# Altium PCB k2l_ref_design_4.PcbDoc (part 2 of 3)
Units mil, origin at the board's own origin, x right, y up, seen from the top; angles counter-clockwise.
Board outline 8000 x 6000 mil, 2 copper layers (Top Layer, Bottom Layer), stack 62 mil thick; 620 components, 466 nets, 2754 pads, 0 vias.
Unrouted connection lines stored in the file: 183.
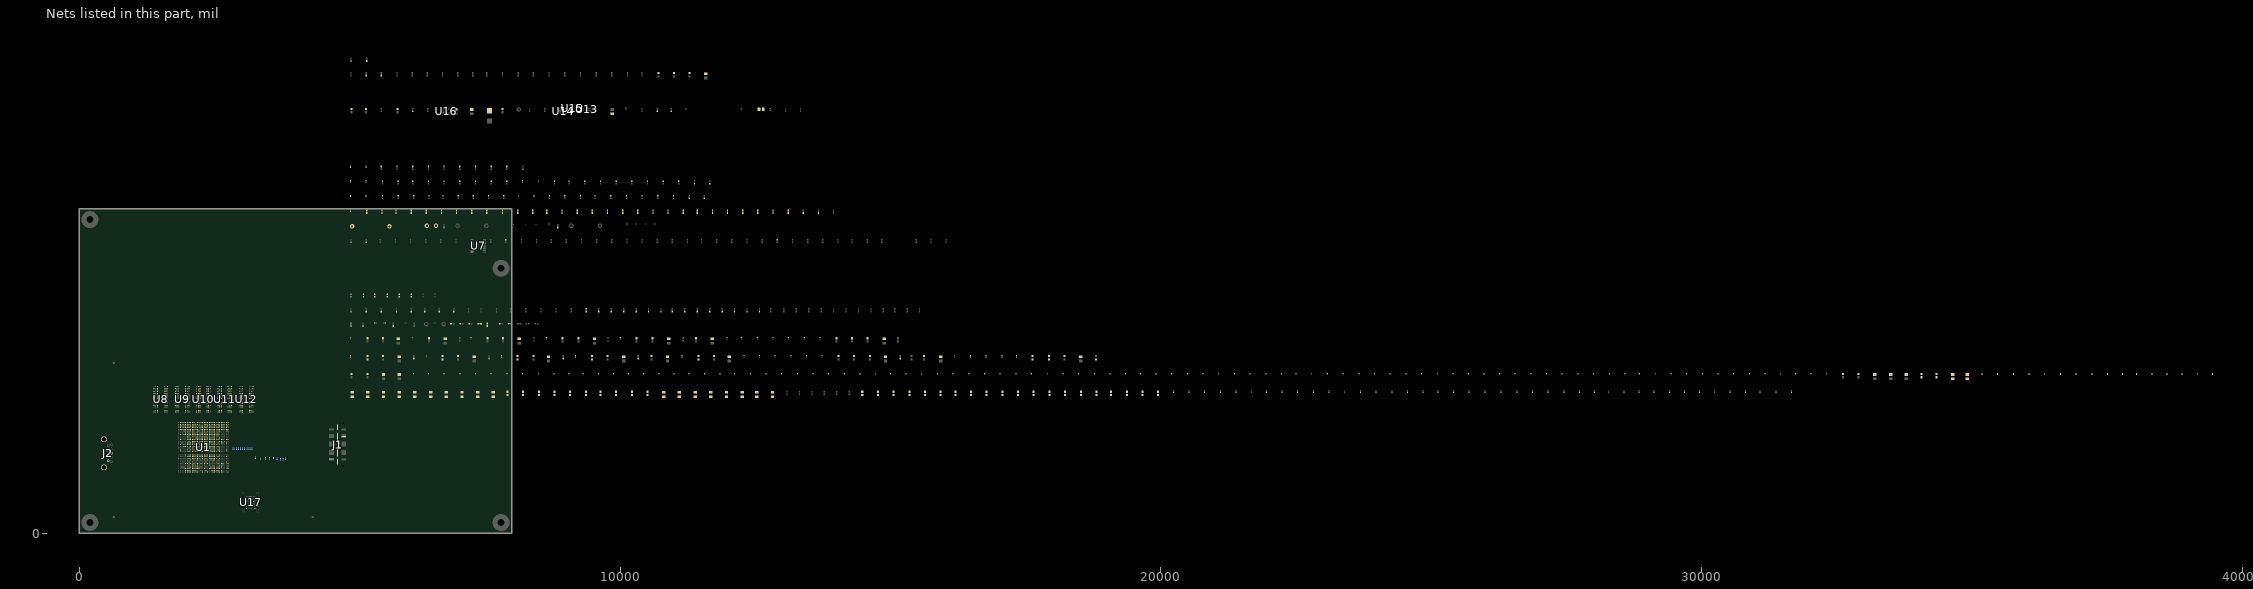
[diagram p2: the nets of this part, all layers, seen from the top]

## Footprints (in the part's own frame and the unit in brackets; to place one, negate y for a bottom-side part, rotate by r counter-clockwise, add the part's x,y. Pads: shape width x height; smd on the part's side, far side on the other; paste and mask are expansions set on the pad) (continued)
BGA900C80P30X30_2500X2500X355 [mm] "BGA, 900-Leads, Body 25.0x25.0mm,  Pitch 0.80mm"
  round 0.45 smd: A1(-11.6,11.6) A2(-10.8,11.6) A3(-10,11.6) A4(-9.2,11.6) A5(-8.4,11.6) A6(-7.6,11.6) A7(-6.8,11.6) A8(-6,11.6) A9(-5.2,11.6) A10(-4.4,11.6) A11(-3.6,11.6) A12(-2.8,11.6) A13(-2,11.6) A14(-1.2,11.6) A15(-0.4,11.6) A16(0.4,11.6) A17(1.2,11.6) A18(2,11.6) A19(2.8,11.6) A20(3.6,11.6) A21(4.4,11.6) A22(5.2,11.6) A23(6,11.6) A24(6.8,11.6) A25(7.6,11.6) A26(8.4,11.6) A27(9.2,11.6) A28(10,11.6) A29(10.8,11.6) A30(11.6,11.6) AA1(-11.6,-4.4) AA2(-10.8,-4.4) AA3(-10,-4.4) AA4(-9.2,-4.4) AA5(-8.4,-4.4) AA6(-7.6,-4.4) AA7(-6.8,-4.4) AA8(-6,-4.4) AA9(-5.2,-4.4) AA10(-4.4,-4.4) AA11(-3.6,-4.4) AA12(-2.8,-4.4) AA13(-2,-4.4) AA14(-1.2,-4.4) AA15(-0.4,-4.4) AA16(0.4,-4.4) AA17(1.2,-4.4) AA18(2,-4.4) AA19(2.8,-4.4) AA20(3.6,-4.4) AA21(4.4,-4.4) AA22(5.2,-4.4) AA23(6,-4.4) AA24(6.8,-4.4) AA25(7.6,-4.4) AA26(8.4,-4.4) AA27(9.2,-4.4) AA28(10,-4.4) AA29(10.8,-4.4) AA30(11.6,-4.4) AB1(-11.6,-5.2) AB2(-10.8,-5.2) AB3(-10,-5.2) AB4(-9.2,-5.2) AB5(-8.4,-5.2) AB6(-7.6,-5.2) AB7(-6.8,-5.2) AB8(-6,-5.2) AB9(-5.2,-5.2) AB10(-4.4,-5.2) AB11(-3.6,-5.2) AB12(-2.8,-5.2) AB13(-2,-5.2) AB14(-1.2,-5.2) AB15(-0.4,-5.2) AB16(0.4,-5.2) AB17(1.2,-5.2) AB18(2,-5.2) AB19(2.8,-5.2) AB20(3.6,-5.2) AB21(4.4,-5.2) AB22(5.2,-5.2) AB23(6,-5.2) AB24(6.8,-5.2) AB25(7.6,-5.2) AB26(8.4,-5.2) AB27(9.2,-5.2) AB28(10,-5.2) AB29(10.8,-5.2) AB30(11.6,-5.2) AC1(-11.6,-6) AC2(-10.8,-6) AC3(-10,-6) AC4(-9.2,-6) AC5(-8.4,-6) AC6(-7.6,-6) AC7(-6.8,-6) AC8(-6,-6) AC9(-5.2,-6) AC10(-4.4,-6) AC11(-3.6,-6) AC12(-2.8,-6) AC13(-2,-6) AC14(-1.2,-6) AC15(-0.4,-6) AC16(0.4,-6) AC17(1.2,-6) AC18(2,-6) AC19(2.8,-6) AC20(3.6,-6) AC21(4.4,-6) AC22(5.2,-6) AC23(6,-6) AC24(6.8,-6) AC25(7.6,-6) AC26(8.4,-6) AC27(9.2,-6) AC28(10,-6) AC29(10.8,-6) AC30(11.6,-6) AD1(-11.6,-6.8) AD2(-10.8,-6.8) AD3(-10,-6.8) AD4(-9.2,-6.8) AD5(-8.4,-6.8) AD6(-7.6,-6.8) AD7(-6.8,-6.8) AD8(-6,-6.8) AD9(-5.2,-6.8) AD10(-4.4,-6.8) AD11(-3.6,-6.8) AD12(-2.8,-6.8) AD13(-2,-6.8) AD14(-1.2,-6.8) AD15(-0.4,-6.8) AD16(0.4,-6.8) AD17(1.2,-6.8) AD18(2,-6.8) AD19(2.8,-6.8) AD20(3.6,-6.8) AD21(4.4,-6.8) AD22(5.2,-6.8) AD23(6,-6.8) AD24(6.8,-6.8) AD25(7.6,-6.8) AD26(8.4,-6.8) AD27(9.2,-6.8) AD28(10,-6.8) AD29(10.8,-6.8) AD30(11.6,-6.8) AE1(-11.6,-7.6) AE2(-10.8,-7.6) AE3(-10,-7.6) AE4(-9.2,-7.6) AE5(-8.4,-7.6) AE6(-7.6,-7.6) AE7(-6.8,-7.6) AE8(-6,-7.6) AE9(-5.2,-7.6) AE10(-4.4,-7.6) AE11(-3.6,-7.6) AE12(-2.8,-7.6) AE13(-2,-7.6) AE14(-1.2,-7.6) AE15(-0.4,-7.6) AE16(0.4,-7.6) AE17(1.2,-7.6) AE18(2,-7.6) AE19(2.8,-7.6) AE20(3.6,-7.6) AE21(4.4,-7.6) AE22(5.2,-7.6) AE23(6,-7.6) AE24(6.8,-7.6) AE25(7.6,-7.6) AE26(8.4,-7.6) AE27(9.2,-7.6) AE28(10,-7.6) AE29(10.8,-7.6) AE30(11.6,-7.6) AF1(-11.6,-8.4) AF2(-10.8,-8.4) AF3(-10,-8.4) AF4(-9.2,-8.4) AF5(-8.4,-8.4) AF6(-7.6,-8.4) AF7(-6.8,-8.4) AF8(-6,-8.4) AF9(-5.2,-8.4) AF10(-4.4,-8.4) AF11(-3.6,-8.4) AF12(-2.8,-8.4) AF13(-2,-8.4) AF14(-1.2,-8.4) AF15(-0.4,-8.4) AF16(0.4,-8.4) AF17(1.2,-8.4) AF18(2,-8.4) AF19(2.8,-8.4) AF20(3.6,-8.4) AF21(4.4,-8.4) AF22(5.2,-8.4) AF23(6,-8.4) AF24(6.8,-8.4) AF25(7.6,-8.4) AF26(8.4,-8.4) AF27(9.2,-8.4) AF28(10,-8.4) AF29(10.8,-8.4) AF30(11.6,-8.4) AG1(-11.6,-9.2) AG2(-10.8,-9.2) AG3(-10,-9.2) AG4(-9.2,-9.2) AG5(-8.4,-9.2) AG6(-7.6,-9.2) AG7(-6.8,-9.2) AG8(-6,-9.2) AG9(-5.2,-9.2) AG10(-4.4,-9.2) AG11(-3.6,-9.2) AG12(-2.8,-9.2) AG13(-2,-9.2) AG14(-1.2,-9.2) AG15(-0.4,-9.2) AG16(0.4,-9.2) AG17(1.2,-9.2) AG18(2,-9.2) AG19(2.8,-9.2) AG20(3.6,-9.2) AG21(4.4,-9.2) AG22(5.2,-9.2) AG23(6,-9.2) AG24(6.8,-9.2) AG25(7.6,-9.2) AG26(8.4,-9.2) AG27(9.2,-9.2) AG28(10,-9.2) AG29(10.8,-9.2) AG30(11.6,-9.2) AH1(-11.6,-10) AH2(-10.8,-10) AH3(-10,-10) AH4(-9.2,-10) AH5(-8.4,-10) AH6(-7.6,-10) AH7(-6.8,-10) AH8(-6,-10) AH9(-5.2,-10) AH10(-4.4,-10) AH11(-3.6,-10) AH12(-2.8,-10) AH13(-2,-10) AH14(-1.2,-10) AH15(-0.4,-10) AH16(0.4,-10) AH17(1.2,-10) AH18(2,-10) AH19(2.8,-10) AH20(3.6,-10) AH21(4.4,-10) AH22(5.2,-10) AH23(6,-10) AH24(6.8,-10) AH25(7.6,-10) AH26(8.4,-10) AH27(9.2,-10) AH28(10,-10) AH29(10.8,-10) AH30(11.6,-10) AJ1(-11.6,-10.8) AJ2(-10.8,-10.8) AJ3(-10,-10.8) AJ4(-9.2,-10.8) AJ5(-8.4,-10.8) AJ6(-7.6,-10.8) AJ7(-6.8,-10.8) AJ8(-6,-10.8) AJ9(-5.2,-10.8) AJ10(-4.4,-10.8) AJ11(-3.6,-10.8) AJ12(-2.8,-10.8) AJ13(-2,-10.8) AJ14(-1.2,-10.8) AJ15(-0.4,-10.8) AJ16(0.4,-10.8) AJ17(1.2,-10.8) AJ18(2,-10.8) AJ19(2.8,-10.8) AJ20(3.6,-10.8) AJ21(4.4,-10.8) AJ22(5.2,-10.8) AJ23(6,-10.8) AJ24(6.8,-10.8) AJ25(7.6,-10.8) AJ26(8.4,-10.8) AJ27(9.2,-10.8) AJ28(10,-10.8) AJ29(10.8,-10.8) AJ30(11.6,-10.8) AK1(-11.6,-11.6) AK2(-10.8,-11.6) AK3(-10,-11.6) AK4(-9.2,-11.6) AK5(-8.4,-11.6) AK6(-7.6,-11.6) AK7(-6.8,-11.6) AK8(-6,-11.6) AK9(-5.2,-11.6) AK10(-4.4,-11.6) AK11(-3.6,-11.6) AK12(-2.8,-11.6) AK13(-2,-11.6) AK14(-1.2,-11.6) AK15(-0.4,-11.6) AK16(0.4,-11.6) AK17(1.2,-11.6) AK18(2,-11.6) AK19(2.8,-11.6) AK20(3.6,-11.6) AK21(4.4,-11.6) AK22(5.2,-11.6) AK23(6,-11.6) AK24(6.8,-11.6) AK25(7.6,-11.6) AK26(8.4,-11.6) AK27(9.2,-11.6) AK28(10,-11.6) AK29(10.8,-11.6) AK30(11.6,-11.6) B1(-11.6,10.8) B2(-10.8,10.8) B3(-10,10.8) B4(-9.2,10.8) B5(-8.4,10.8) B6(-7.6,10.8) B7(-6.8,10.8) B8(-6,10.8) B9(-5.2,10.8) B10(-4.4,10.8) B11(-3.6,10.8) B12(-2.8,10.8) B13(-2,10.8) B14(-1.2,10.8) B15(-0.4,10.8) B16(0.4,10.8) B17(1.2,10.8) B18(2,10.8) B19(2.8,10.8) B20(3.6,10.8) B21(4.4,10.8) B22(5.2,10.8) B23(6,10.8) B24(6.8,10.8) B25(7.6,10.8) B26(8.4,10.8) B27(9.2,10.8) B28(10,10.8) B29(10.8,10.8) B30(11.6,10.8) C1(-11.6,10) C2(-10.8,10) C3(-10,10) C4(-9.2,10) C5(-8.4,10) C6(-7.6,10) C7(-6.8,10) C8(-6,10) C9(-5.2,10) C10(-4.4,10) C11(-3.6,10) C12(-2.8,10) C13(-2,10) C14(-1.2,10) C15(-0.4,10) C16(0.4,10) C17(1.2,10) C18(2,10) C19(2.8,10) C20(3.6,10) C21(4.4,10) C22(5.2,10) C23(6,10) C24(6.8,10) C25(7.6,10) C26(8.4,10) C27(9.2,10) C28(10,10) C29(10.8,10) C30(11.6,10) D1(-11.6,9.2) D2(-10.8,9.2) D3(-10,9.2) D4(-9.2,9.2) D5(-8.4,9.2) D6(-7.6,9.2) D7(-6.8,9.2) D8(-6,9.2) D9(-5.2,9.2) D10(-4.4,9.2) D11(-3.6,9.2) D12(-2.8,9.2) D13(-2,9.2) D14(-1.2,9.2) D15(-0.4,9.2) D16(0.4,9.2) D17(1.2,9.2) D18(2,9.2) D19(2.8,9.2) D20(3.6,9.2) D21(4.4,9.2) D22(5.2,9.2) D23(6,9.2) D24(6.8,9.2) D25(7.6,9.2) D26(8.4,9.2) D27(9.2,9.2) D28(10,9.2) D29(10.8,9.2) D30(11.6,9.2) E1(-11.6,8.4) E2(-10.8,8.4) E3(-10,8.4) E4(-9.2,8.4) E5(-8.4,8.4) E6(-7.6,8.4) E7(-6.8,8.4) E8(-6,8.4) E9(-5.2,8.4) E10(-4.4,8.4) E11(-3.6,8.4) E12(-2.8,8.4) E13(-2,8.4) E14(-1.2,8.4) E15(-0.4,8.4) E16(0.4,8.4) E17(1.2,8.4) E18(2,8.4) E19(2.8,8.4) E20(3.6,8.4) E21(4.4,8.4) E22(5.2,8.4) E23(6,8.4) E24(6.8,8.4) E25(7.6,8.4) E26(8.4,8.4) E27(9.2,8.4) E28(10,8.4) E29(10.8,8.4) E30(11.6,8.4) F1(-11.6,7.6) F2(-10.8,7.6) F3(-10,7.6) F4(-9.2,7.6) F5(-8.4,7.6) F6(-7.6,7.6) F7(-6.8,7.6) F8(-6,7.6) F9(-5.2,7.6) F10(-4.4,7.6) F11(-3.6,7.6) F12(-2.8,7.6) F13(-2,7.6) F14(-1.2,7.6) F15(-0.4,7.6) F16(0.4,7.6) F17(1.2,7.6) F18(2,7.6) F19(2.8,7.6) F20(3.6,7.6) F21(4.4,7.6) F22(5.2,7.6) F23(6,7.6) F24(6.8,7.6) F25(7.6,7.6) F26(8.4,7.6) F27(9.2,7.6) F28(10,7.6) F29(10.8,7.6) F30(11.6,7.6) G1(-11.6,6.8) G2(-10.8,6.8) G3(-10,6.8) G4(-9.2,6.8) G5(-8.4,6.8) G6(-7.6,6.8) G7(-6.8,6.8) G8(-6,6.8) G9(-5.2,6.8) G10(-4.4,6.8) G11(-3.6,6.8) G12(-2.8,6.8) G13(-2,6.8) G14(-1.2,6.8) G15(-0.4,6.8) G16(0.4,6.8) G17(1.2,6.8) G18(2,6.8) G19(2.8,6.8) G20(3.6,6.8) G21(4.4,6.8) G22(5.2,6.8) G23(6,6.8) G24(6.8,6.8) G25(7.6,6.8) G26(8.4,6.8) G27(9.2,6.8) G28(10,6.8) G29(10.8,6.8) G30(11.6,6.8) H1(-11.6,6) H2(-10.8,6) H3(-10,6) H4(-9.2,6) H5(-8.4,6) H6(-7.6,6) H7(-6.8,6) H8(-6,6) H9(-5.2,6) H10(-4.4,6) H11(-3.6,6) H12(-2.8,6) H13(-2,6) H14(-1.2,6) H15(-0.4,6) H16(0.4,6) H17(1.2,6) H18(2,6) H19(2.8,6) H20(3.6,6) H21(4.4,6) H22(5.2,6) H23(6,6) H24(6.8,6) H25(7.6,6) H26(8.4,6) H27(9.2,6) H28(10,6) H29(10.8,6) H30(11.6,6) J1(-11.6,5.2) J2(-10.8,5.2) J3(-10,5.2) J4(-9.2,5.2) J5(-8.4,5.2) J6(-7.6,5.2) J7(-6.8,5.2) J8(-6,5.2) J9(-5.2,5.2) J10(-4.4,5.2) J11(-3.6,5.2) J12(-2.8,5.2) J13(-2,5.2) J14(-1.2,5.2) J15(-0.4,5.2) J16(0.4,5.2) J17(1.2,5.2) J18(2,5.2) J19(2.8,5.2) J20(3.6,5.2) J21(4.4,5.2) J22(5.2,5.2) J23(6,5.2) J24(6.8,5.2) J25(7.6,5.2) J26(8.4,5.2) J27(9.2,5.2) J28(10,5.2) J29(10.8,5.2) J30(11.6,5.2) K1(-11.6,4.4) K2(-10.8,4.4) K3(-10,4.4) K4(-9.2,4.4) K5(-8.4,4.4) K6(-7.6,4.4) K7(-6.8,4.4) K8(-6,4.4) K9(-5.2,4.4) K10(-4.4,4.4) K11(-3.6,4.4) K12(-2.8,4.4) K13(-2,4.4) K14(-1.2,4.4) K15(-0.4,4.4) K16(0.4,4.4) K17(1.2,4.4) K18(2,4.4) K19(2.8,4.4) K20(3.6,4.4) K21(4.4,4.4) K22(5.2,4.4) K23(6,4.4) K24(6.8,4.4) K25(7.6,4.4) K26(8.4,4.4) K27(9.2,4.4) K28(10,4.4) K29(10.8,4.4) K30(11.6,4.4) L1(-11.6,3.6) L2(-10.8,3.6) L3(-10,3.6) L4(-9.2,3.6) L5(-8.4,3.6) L6(-7.6,3.6) L7(-6.8,3.6) L8(-6,3.6) L9(-5.2,3.6) L10(-4.4,3.6) L11(-3.6,3.6) L12(-2.8,3.6) L13(-2,3.6) L14(-1.2,3.6) L15(-0.4,3.6) L16(0.4,3.6) L17(1.2,3.6) L18(2,3.6) L19(2.8,3.6) L20(3.6,3.6) L21(4.4,3.6) L22(5.2,3.6) L23(6,3.6) L24(6.8,3.6) L25(7.6,3.6) L26(8.4,3.6) L27(9.2,3.6) L28(10,3.6) L29(10.8,3.6) L30(11.6,3.6) M1(-11.6,2.8) M2(-10.8,2.8) M3(-10,2.8) M4(-9.2,2.8) M5(-8.4,2.8) M6(-7.6,2.8) M7(-6.8,2.8) M8(-6,2.8) M9(-5.2,2.8) M10(-4.4,2.8) M11(-3.6,2.8) M12(-2.8,2.8) M13(-2,2.8) M14(-1.2,2.8) M15(-0.4,2.8) M16(0.4,2.8) M17(1.2,2.8) M18(2,2.8) M19(2.8,2.8) M20(3.6,2.8) M21(4.4,2.8) M22(5.2,2.8) M23(6,2.8) M24(6.8,2.8) M25(7.6,2.8) M26(8.4,2.8) M27(9.2,2.8) M28(10,2.8) M29(10.8,2.8) M30(11.6,2.8) N1(-11.6,2) N2(-10.8,2) N3(-10,2) N4(-9.2,2) N5(-8.4,2) N6(-7.6,2) N7(-6.8,2) N8(-6,2) N9(-5.2,2) N10(-4.4,2) N11(-3.6,2) N12(-2.8,2) N13(-2,2) N14(-1.2,2) N15(-0.4,2) N16(0.4,2) N17(1.2,2) N18(2,2) N19(2.8,2) N20(3.6,2) N21(4.4,2) N22(5.2,2) N23(6,2) N24(6.8,2) N25(7.6,2) N26(8.4,2) N27(9.2,2) N28(10,2) N29(10.8,2) N30(11.6,2) P1(-11.6,1.2) P2(-10.8,1.2) P3(-10,1.2) P4(-9.2,1.2) P5(-8.4,1.2) P6(-7.6,1.2) P7(-6.8,1.2) P8(-6,1.2) P9(-5.2,1.2) P10(-4.4,1.2) P11(-3.6,1.2) P12(-2.8,1.2) P13(-2,1.2) P14(-1.2,1.2) P15(-0.4,1.2) P16(0.4,1.2) P17(1.2,1.2) P18(2,1.2) P19(2.8,1.2) P20(3.6,1.2) P21(4.4,1.2) P22(5.2,1.2) P23(6,1.2) P24(6.8,1.2) P25(7.6,1.2) P26(8.4,1.2) P27(9.2,1.2) P28(10,1.2) P29(10.8,1.2) P30(11.6,1.2) R1(-11.6,0.4) R2(-10.8,0.4) R3(-10,0.4) R4(-9.2,0.4) R5(-8.4,0.4) R6(-7.6,0.4) R7(-6.8,0.4) R8(-6,0.4) R9(-5.2,0.4) R10(-4.4,0.4) R11(-3.6,0.4) R12(-2.8,0.4) R13(-2,0.4) R14(-1.2,0.4) R15(-0.4,0.4) R16(0.4,0.4) R17(1.2,0.4) R18(2,0.4) R19(2.8,0.4) R20(3.6,0.4) R21(4.4,0.4) R22(5.2,0.4) R23(6,0.4) R24(6.8,0.4) R25(7.6,0.4) R26(8.4,0.4) R27(9.2,0.4) R28(10,0.4) R29(10.8,0.4) R30(11.6,0.4) T1(-11.6,-0.4) T2(-10.8,-0.4) T3(-10,-0.4) T4(-9.2,-0.4) T5(-8.4,-0.4) T6(-7.6,-0.4) T7(-6.8,-0.4) T8(-6,-0.4) T9(-5.2,-0.4) T10(-4.4,-0.4) T11(-3.6,-0.4) T12(-2.8,-0.4) T13(-2,-0.4) T14(-1.2,-0.4) T15(-0.4,-0.4) T16(0.4,-0.4) T17(1.2,-0.4) T18(2,-0.4) T19(2.8,-0.4) T20(3.6,-0.4) T21(4.4,-0.4) T22(5.2,-0.4) T23(6,-0.4) T24(6.8,-0.4) T25(7.6,-0.4) T26(8.4,-0.4) T27(9.2,-0.4) T28(10,-0.4) T29(10.8,-0.4) T30(11.6,-0.4) U1(-11.6,-1.2) U2(-10.8,-1.2) U3(-10,-1.2) U4(-9.2,-1.2) U5(-8.4,-1.2) U6(-7.6,-1.2) U7(-6.8,-1.2) U8(-6,-1.2) U9(-5.2,-1.2) U10(-4.4,-1.2) U11(-3.6,-1.2) U12(-2.8,-1.2) U13(-2,-1.2) U14(-1.2,-1.2) U15(-0.4,-1.2) U16(0.4,-1.2) U17(1.2,-1.2) U18(2,-1.2) U19(2.8,-1.2) U20(3.6,-1.2) U21(4.4,-1.2) U22(5.2,-1.2) U23(6,-1.2) U24(6.8,-1.2) U25(7.6,-1.2) U26(8.4,-1.2) U27(9.2,-1.2) U28(10,-1.2) U29(10.8,-1.2) U30(11.6,-1.2) V1(-11.6,-2) V2(-10.8,-2) V3(-10,-2) V4(-9.2,-2) V5(-8.4,-2) V6(-7.6,-2) V7(-6.8,-2) V8(-6,-2) V9(-5.2,-2) V10(-4.4,-2) V11(-3.6,-2) V12(-2.8,-2) V13(-2,-2) V14(-1.2,-2) V15(-0.4,-2) V16(0.4,-2) V17(1.2,-2) V18(2,-2) V19(2.8,-2) V20(3.6,-2) V21(4.4,-2) V22(5.2,-2) V23(6,-2) V24(6.8,-2) V25(7.6,-2) V26(8.4,-2) V27(9.2,-2) V28(10,-2) V29(10.8,-2) V30(11.6,-2) W1(-11.6,-2.8) W2(-10.8,-2.8) W3(-10,-2.8) W4(-9.2,-2.8) W5(-8.4,-2.8) W6(-7.6,-2.8) W7(-6.8,-2.8) W8(-6,-2.8) W9(-5.2,-2.8) W10(-4.4,-2.8) W11(-3.6,-2.8) W12(-2.8,-2.8) W13(-2,-2.8) W14(-1.2,-2.8) W15(-0.4,-2.8) W16(0.4,-2.8) W17(1.2,-2.8) W18(2,-2.8) W19(2.8,-2.8) W20(3.6,-2.8) W21(4.4,-2.8) W22(5.2,-2.8) W23(6,-2.8) W24(6.8,-2.8) W25(7.6,-2.8) W26(8.4,-2.8) W27(9.2,-2.8) W28(10,-2.8) W29(10.8,-2.8) W30(11.6,-2.8) Y1(-11.6,-3.6) Y2(-10.8,-3.6) Y3(-10,-3.6) Y4(-9.2,-3.6) Y5(-8.4,-3.6) Y6(-7.6,-3.6) Y7(-6.8,-3.6) Y8(-6,-3.6) Y9(-5.2,-3.6) Y10(-4.4,-3.6) Y11(-3.6,-3.6) Y12(-2.8,-3.6) Y13(-2,-3.6) Y14(-1.2,-3.6) Y15(-0.4,-3.6) Y16(0.4,-3.6) Y17(1.2,-3.6) Y18(2,-3.6) Y19(2.8,-3.6) Y20(3.6,-3.6) Y21(4.4,-3.6) Y22(5.2,-3.6) Y23(6,-3.6) Y24(6.8,-3.6) Y25(7.6,-3.6) Y26(8.4,-3.6) Y27(9.2,-3.6) Y28(10,-3.6) Y29(10.8,-3.6) Y30(11.6,-3.6)
  silkscreen extent -13.27,-12.5 12.5,12.5, body extent -12.5,-12.5 12.5,12.5, height 3.55
DBV0005A_N [mm] "SOT23, 5-Leads, Body 2.9x1.6mm, Pitch 0.95mm, Lead Span 2.8mm, IPC Medium Density"
  rrect17% 1x0.6 smd: 1(-1.375,0.95) 2(-1.375,0) 3(-1.375,-0.95) 4(1.375,-0.95) 5(1.375,0.95)
  silkscreen extent -1.63,-1.55 0.38,1.55, body extent -1.42,-1.46 1.42,1.46, height 1.09
Fiducial10-20 [mm]
  round 1 smd mask+0.5: 1(0,0)
  Top Layer keep-out circle w1.178: c0,0 r0.5
Keystone_1902C [mil] "Hex Standoff, 4-40 threaded, nylon"
  body extent -145,-126 146,126, height 501
MICT-HA-96 [mm] "BGA, 96-Balls, Body 14x9mm, Pitch 0.8mm"
  round 0.4 smd: A1(-3.2,6) A2(-2.4,6) A3(-1.6,6) A7(1.6,6) A8(2.4,6) A9(3.2,6) B1(-3.2,5.2) B2(-2.4,5.2) B3(-1.6,5.2) B7(1.6,5.2) B8(2.4,5.2) B9(3.2,5.2) C1(-3.2,4.4) C2(-2.4,4.4) C3(-1.6,4.4) C7(1.6,4.4) C8(2.4,4.4) C9(3.2,4.4) D1(-3.2,3.6) D2(-2.4,3.6) D3(-1.6,3.6) D7(1.6,3.6) D8(2.4,3.6) D9(3.2,3.6) E1(-3.2,2.8) E2(-2.4,2.8) E3(-1.6,2.8) E7(1.6,2.8) E8(2.4,2.8) E9(3.2,2.8) F1(-3.2,2) F2(-2.4,2) F3(-1.6,2) F7(1.6,2) F8(2.4,2) F9(3.2,2) G1(-3.2,1.2) G2(-2.4,1.2) G3(-1.6,1.2) G7(1.6,1.2) G8(2.4,1.2) G9(3.2,1.2) H1(-3.2,0.4) H2(-2.4,0.4) H3(-1.6,0.4) H7(1.6,0.4) H8(2.4,0.4) H9(3.2,0.4) J1(-3.2,-0.4) J2(-2.4,-0.4) J3(-1.6,-0.4) J7(1.6,-0.4) J8(2.4,-0.4) J9(3.2,-0.4) K1(-3.2,-1.2) K2(-2.4,-1.2) K3(-1.6,-1.2) K7(1.6,-1.2) K8(2.4,-1.2) K9(3.2,-1.2) L1(-3.2,-2) L2(-2.4,-2) L3(-1.6,-2) L7(1.6,-2) L8(2.4,-2) L9(3.2,-2) M1(-3.2,-2.8) M2(-2.4,-2.8) M3(-1.6,-2.8) M7(1.6,-2.8) M8(2.4,-2.8) M9(3.2,-2.8) N1(-3.2,-3.6) N2(-2.4,-3.6) N3(-1.6,-3.6) N7(1.6,-3.6) N8(2.4,-3.6) N9(3.2,-3.6) P1(-3.2,-4.4) P2(-2.4,-4.4) P3(-1.6,-4.4) P7(1.6,-4.4) P8(2.4,-4.4) P9(3.2,-4.4) R1(-3.2,-5.2) R2(-2.4,-5.2) R3(-1.6,-5.2) R7(1.6,-5.2) R8(2.4,-5.2) R9(3.2,-5.2) T1(-3.2,-6) T2(-2.4,-6) T3(-1.6,-6) T7(1.6,-6) T8(2.4,-6) T9(3.2,-6)
  silkscreen extent -5.27,-7 4.5,7, body extent -4.5,-7 4.5,7, height 0.1
"NY PMS 440 0025 PH" [mm] "4-40 nylon screw and mounting hole"
  round 8 hole 3.2: 1(0,0)
  body extent -3.3,-3.3 3.3,3.3, height 2.69
PW0020A_N [mm] "TSOP, 20-Leads, Body 6.5x4.4mm, Pitch 0.65mm, IPC Medium Density"
  oval 1.4x0.45 smd: 1(-2.95,2.925) 2(-2.95,2.275) 3(-2.95,1.625) 4(-2.95,0.975) 5(-2.95,0.325) 6(-2.95,-0.325) 7(-2.95,-0.975) 8(-2.95,-1.625) 9(-2.95,-2.275) 10(-2.95,-2.925) 11(2.95,-2.925) 12(2.95,-2.275) 13(2.95,-1.625) 14(2.95,-0.975) 15(2.95,-0.325) 16(2.95,0.325) 17(2.95,0.975) 18(2.95,1.625) 19(2.95,2.275) 20(2.95,2.925)
  silkscreen extent -3.5,-3.3 1.85,3.4, body extent -3.21,-3.25 3.21,3.25, height 1
Samtec_QSH-030-01-X-D-A [mm] "Receptacle, 0.5 mm, 30x2, TH"
  rect 2.27x0.279 smd: 1(-2.865,7.25) 2(2.865,7.25) 3(-2.865,6.75) 4(2.865,6.75) 5(-2.865,6.25) 6(2.865,6.25) 7(-2.865,5.75) 8(2.865,5.75) 9(-2.865,5.25) 10(2.865,5.25) 11(-2.865,4.75) 12(2.865,4.75) 13(-2.865,4.25) 14(2.865,4.25) 15(-2.865,3.75) 16(2.865,3.75) 17(-2.865,3.25) 18(2.865,3.25) 19(-2.865,2.75) 20(2.865,2.75) 21(-2.865,2.25) 22(2.865,2.25) 23(-2.865,1.75) 24(2.865,1.75) 25(-2.865,1.25) 26(2.865,1.25) 27(-2.865,0.75) 28(2.865,0.75) 29(-2.865,0.25) 30(2.865,0.25) 31(-2.865,-0.25) 32(2.865,-0.25) 33(-2.865,-0.75) 34(2.865,-0.75) 35(-2.865,-1.25) 36(2.865,-1.25) 37(-2.865,-1.75) 38(2.865,-1.75) 39(-2.865,-2.25) 40(2.865,-2.25) 41(-2.865,-2.75) 42(2.865,-2.75) 43(-2.865,-3.25) 44(2.865,-3.25) 45(-2.865,-3.75) 46(2.865,-3.75) 47(-2.865,-4.25) 48(2.865,-4.25) 49(-2.865,-4.75) 50(2.865,-4.75) 51(-2.865,-5.25) 52(2.865,-5.25) 53(-2.865,-5.75) 54(2.865,-5.75) 55(-2.865,-6.25) 56(2.865,-6.25) 57(-2.865,-6.75) 58(2.865,-6.75) 59(-2.865,-7.25) 60(2.865,-7.25)
  round 0 hole 1.02 unplated: MH1(2.67,10.065) MH2(2.67,-10.065)
  rect 0.43x2.54 smd: MP1(0,8.065) MP4(0,-8.065)
  rect 0.43x4.7 smd: MP2(0,3.175) MP3(0,-3.175)
  silkscreen extent -3.9,-10.66 3.62,10.66, body extent -3.75,-10.64 3.75,10.67, height 3.25
TESTPOINT [mil]
  round 80 hole 37.99: 1(0,0)
UDFN-14 [mm] "DFN, 14-Leads, Body 3.50x1.35mm, Pitch 0.50mm, IPC Medium Density"
  rect 0.3x0.4 smd mask+0.05: 1(-0.01,0) 2(-0.51,0) 3(-1.01,0) 4(-1.51,0) 5(-2.01,0) 6(-2.51,0) 7(-3.01,0) 8(-3.01,-1.05) 9(-2.51,-1.05) 10(-2.01,-1.05) 11(-1.51,-1.05) 12(-1.01,-1.05) 13(-0.51,-1.05) 14(-0.01,-1.05)
  silkscreen extent -3.31,-1.25 0.74,0.25, body extent -3.31,-1.25 0.29,0.2, height 0.6
VBGA63_NANDx8 [mm] "BGA, 81-Leads, Body 9.00x11.00mmx1.00mm, Pitch 0.80mm"
  round 0.41 smd: A1(-3.6,4.4) A2(-2.8,4.4) A9(2.8,4.4) A10(3.6,4.4) B1(-3.6,3.6) B9(2.8,3.6) B10(3.6,3.6) C3(-2,2.8) C4(-1.2,2.8) C5(-0.4,2.8) C6(0.4,2.8) C7(1.2,2.8) C8(2,2.8) D3(-2,2) D4(-1.2,2) D5(-0.4,2) D6(0.4,2) D7(1.2,2) D8(2,2) E3(-2,1.2) E4(-1.2,1.2) E5(-0.4,1.2) E6(0.4,1.2) E7(1.2,1.2) E8(2,1.2) F3(-2,0.4) F4(-1.2,0.4) F5(-0.4,0.4) F6(0.4,0.4) F7(1.2,0.4) F8(2,0.4) G3(-2,-0.4) G4(-1.2,-0.4) G5(-0.4,-0.4) G6(0.4,-0.4) G7(1.2,-0.4) G8(2,-0.4) H3(-2,-1.2) H4(-1.2,-1.2) H5(-0.4,-1.2) H6(0.4,-1.2) H7(1.2,-1.2) H8(2,-1.2) J3(-2,-2) J4(-1.2,-2) J5(-0.4,-2) J6(0.4,-2) J7(1.2,-2) J8(2,-2) K3(-2,-2.8) K4(-1.2,-2.8) K5(-0.4,-2.8) K6(0.4,-2.8) K7(1.2,-2.8) K8(2,-2.8) L1(-3.6,-3.6) L2(-2.8,-3.6) L9(2.8,-3.6) L10(3.6,-3.6) M1(-3.6,-4.4) M2(-2.8,-4.4) M9(2.8,-4.4) M10(3.6,-4.4)
  silkscreen extent -5.27,-5.5 4.5,5.5, body extent -4.5,-5.5 4.5,5.5, height 1
YZV0004ADAD [mm] "BGA, 4-Leads, Pitch 0.5mm"
  round 0.23 smd mask+0.04: A1(-0.25,0.25) A2(0.25,0.25) B1(-0.25,-0.25) B2(0.25,-0.25)
  silkscreen extent -0.63,0.51 -0.53,0.61, body extent -0.46,-0.46 0.46,0.46, height 0.56

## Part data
C1 C2 C3 C4 C236 C237 C238 C239 C240 C241 C242 C243 C244 C245 C302 C303 C304 C305 C306 C329 C330 C331 C332 C333 C334 C335 C336 C337 C338 C339 C340 C341 C342 C343 C344 C345 C346 C347 C348 C349 C350 C351 C352 C353 C354 C381 C382 C383 C384 C385 C386 C387 C388 C389 C390 C391 C392 C393 C394 C395 C396 C397 C398 C399 C400 C505 C506 C507 C517 C518 C528 C529 C539 C540 C550 C551: "CAP, CERM, 0.1 µF, 6.3 V, +/- 10%, X5R, 0201"
C5 C6 C7 C8 C9 C10 C11 C12 C563 C564: "CAP, CERM, 0.1 µF, 10 V, +/- 10%, X5R, 0201"
C185 C186 C187 C188 C189 C190 C191 C192 C193 C194 C195 C196 C197 C198 C199 C200 C201 C202 C203 C204: "CAP, CERM, 0.01 µF, 6.3 V, +/- 10%, X7R, 0201"
C205 C206 C207 C208 C209 C210 C211 C212 C213 C214 C215 C216 C217 C218 C219 C220 C221 C222 C223 C224: "CAP, CERM, 0.022 µF, 6.3 V, +/- 10%, X5R, 0201"
C225 C226 C227 C228 C229 C230 C231 C232 C233 C234 C235: "CAP, CERM, 0.047 µF, 6.3 V, +/- 10%, X5R, 0201"
C246 C247 C248 C249 C250 C251 C252 C253 C254 C255: "CAP, CERM, 0.22 µF, 10 V, +/- 10%, X5R, 0603"
C256 C257 C258 C259 C260 C261 C262 C263 C264 C265: "CAP, CERM, 0.47 µF, 10 V, +/- 10%, X5R, 0603"
C266 C267 C268 C269 C270 C271 C272 C273 C274 C275 C319 C320 C324 C325 C424 C425 C435 C437 C441 C451 C453 C457 C461 C465 C469 C480 C482 C486 C490 C494 C497 C501 C566 C570 C571 C572 C573 C574 C575: "CAP, CERM, 1 µF, 6.3 V, +/- 10%, X7R, 0603"
C276 C277 C278 C279 C280 C281 C282 C283 C436 C438 C442 C452 C454 C458 C462 C466 C470 C481 C483 C487 C491 C495 C498 C502 C576: "CAP, CERM, 10 µF, 6.3 V, +80/-20%, Y5V, 0805"
C292 C293 C294 C295 C296 C568: "CAP, CERM, 22 µF, 4 V, +/- 20%, X6S, 0805"
C297 C298 C299 C300 C301 C569: "CAP, CERM, 47 µF, 6.3 V, +/- 20%, X5R, 0805"
C307 C308 C309 C310 C311 C371 C372 C373 C374 C375 C376 C377 C378 C379 C380 C411 C412 C413 C414 C415 C416 C417 C418 C419 C420 C428 C429 C430 C431 C432 C439 C443 C444 C445 C446 C447 C448 C455 C459 C463 C467 C471 C472 C473 C474 C475 C476 C477 C484 C488 C492 C496 C499 C565: "CAP, CERM, 0.01 µF, 6.3 V, +/- 10%, X5R, 0201"
C312 C313 C314 C315 C316 C317: "CAP, CERM, 1000 pF, 16 V, +/- 10%, X7R, 0201"
C321 C322 C326 C327 C328 C426 C427: "CAP, CERM, 10 µF, 6.3 V, +/- 10%, X7R, 0805"
C355 C356 C357 C358 C359 C360 C361 C362 C363 C364 C365 C366 C367 C368 C369 C370 C401 C402 C403 C404 C405 C406 C407 C408 C409 C410: "CAP, CERM, 0.022 µF, 4 V, +/- 10%, X6S, 0201"
C433 C434 C440 C449 C450 C456 C460 C464 C468 C478 C479 C485 C489 C493 C500: "CAP, CERM, 0.1 µF, 6.3 V, +/- 10%, X7R, 0603"
C503 C504 C508 C509 C510 C511 C512 C513 C514 C515 C516 C519 C520 C521 C522 C523 C524 C525 C526 C527 C530 C531 C532 C533 C534 C535 C536 C537 C538 C541 C542 C543 C544 C545 C546 C547 C548 C549 C552 C553 C554 C555 C556 C557 C558 C559 C560: "CAP, CERM, 0.1 µF, 6.3 V, +/- 10%, B, 0402"
C567: "CAP, TA, 100 µF, 10 V, +/- 10%, 0.9 ohm, SMD"
DAC_SYNCBN1 DAC_SYNCBP1 JESDCLK1 JESDCLK2 JESDCLK3 JESDCLK4 K1 K2 K3 K4 K15: "TEST POINT.  No entry in BOM."
FID1 FID2 FID3: "Fiducial mark.  There is nothing to buy or mount."
H1 H2 H3 H4: "Machine Screw, Round, #4-40 x 1/4, Nylon, Philips panhead"
H5 H6 H7 H8: "Standoff, Hex, 0.5\"L #4-40 Nylon"
J1: "Receptacle, 0.5 mm, 30x2, Gold, TH"
J2: "Connector, Receptacle, USB 3.1 Type A, R/A, TH"
L20 L22 L27: "Ferrite Bead, 120 ohm @ 100 MHz, 3 A, 0603"
L21 L23 L24 L25 L26 L28 L29 L30 L31: "Ferrite Bead, 120 ohm @ 100 MHz, 0.55 A, 0402"
L32: "Ferrite Bead, 30 ohm @ 100 MHz, 6 A, 0805"
R1 R2 R3 R15 R16 R65 R66 R67 R68 R69 R70 R71 R72 R73 R74 R75 R76 R77 R78 R79 R80 R81 R82 R83 R84 R99 R100 R101 R102 R103 R104 R105 R106 R115 R123 R150 R196 R197 R213 R215 R216 R219 R220: "RES, 4.75 k, 1%, 0.063 W, 0402"
R4 R5 R6 R7 R8 R9 R10 R12 R13 R14 R85 R86 R87 R88 R89 R90 R91 R92 R93 R94 R95 R96 R97 R98 R107 R108 R109 R110 R111 R112 R113 R114 R188 R189 R191 R192 R194 R199: "RES, 1.00 k, 1%, 0.063 W, 0402"
R11 R17 R18 R19 R20 R21 R22 R118 R119 R120 R121 R122 R124 R125 R126 R127 R128 R129 R130 R131 R132 R133 R134 R135 R136 R137 R138 R139 R140 R141 R142 R143 R144 R145 R146 R147 R148 R149 R151 R201 R202 R203 R204 R205 R206 R207 R208 R209 R210 R211 R212 R214 R217 R218: "RES, 10.0, 1%, 0.063 W, 0402"
R23 R24 R221 R222: "RES, 3.0 k, 5%, 0.063 W, 0402"
R116 R117: "RES, 100, 1%, 0.063 W, 0402"
R152 R153 R154 R155 R156 R157 R158 R159 R160 R161 R162 R163 R164 R165 R166 R167 R168 R169 R170 R171 R172 R173 R174 R175 R176 R177 R178 R179: "RES, 39.2, 1%, 0.063 W, 0402"
R180 R181 R182 R183 R184 R185 R186 R187: "RES, 240, 5%, 0.063 W, 0402"
R190: "RES, 100, 1%, 0.05 W, 0201"
R193 R198 R200: "RES, 0, 5%, 0.063 W, 0402"
R195: "RES, 200, 0.1%, 0.125 W, 0805"
U1: library part lamarr_soc_TCI6630K2L, "Smallcell Baseband Processor with 4 C66x DSP Cores / 2 ARM A15 Cores / JESD / CPRI...etc"
U7: "OCTAL BUFFER/DRIVER WITH 3-STATE OUTPUTS, PW0020A"
U8 U9 U10 U11 U12: "4Gb DDR3-1600 SDRAM, 256Mb x 16, 1.25ns, 1.35V, 0 to 95 degC, 96-Ball FBGA, Pb-Free"
U13: "TVS DIODE 5VWM 7VC 14UDFN"
U14: "Current-Limited, Power-Distribution Switches, DBV0005A"
U15: "Ultra-small, Low On Resistance Load Switch with Controlled Turn-on, YZV0004ADAD"
U16: "SINGLE BUFFER/DRIVER WITH OPEN-DRAIN OUTPUT, DBV0005A"
U17: "16Gbit, x8, 1.8V NAND Flash Memory"

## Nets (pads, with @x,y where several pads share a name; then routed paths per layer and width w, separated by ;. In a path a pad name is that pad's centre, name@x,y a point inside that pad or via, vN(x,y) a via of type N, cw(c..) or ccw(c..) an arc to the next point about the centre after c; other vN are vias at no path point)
DAC_SYNCBN: DAC_SYNCBN1.1 U1.AG13
DAC_SYNCBP: DAC_SYNCBP1.1 U1.AG12
GND: C185.2 C186.2 C187.2 C188.2 C189.2 C190.2 C191.2 C192.2 C193.2 C194.2 C195.2 C196.2 C197.2 C198.2 C199.2 C200.2 C201.2 C202.2 C203.2 C204.2 C205.2 C206.2 C207.2 C208.2 C209.2 C210.2 C211.2 C212.2 C213.2 C214.2 C215.2 C216.2 C217.2 C218.2 C219.2 C220.2 C221.2 C222.2 C223.2 C224.2 C225.2 C226.2 C227.2 C228.2 C229.2 C230.2 C231.2 C232.2 C233.2 C234.2 C235.2 C236.2 C237.2 C238.2 C239.2 C240.2 C241.2 C242.2 C243.2 C244.2 C245.2 C246.2 C247.2 C248.2 C249.2 C250.2 C251.2 C252.2 C253.2 C254.2 C255.2 C256.2 C257.2 C258.2 C259.2 C260.2 C261.2 C262.2 C263.2 C264.2 C265.2 C266.2 C267.2 C268.2 C269.2 C270.2 C271.2 C272.2 C273.2 C274.2 C275.2 C276.2 C277.2 C278.2 C279.2 C280.2 C281.2 C282.2 C283.2 C292.2 C293.2 C294.2 C295.2 C296.2 C297.2 C298.2 C299.2 C300.2 C301.2 C302.2 C303.2 C304.2 C305.2 C306.2 C307.2 C308.2 C309.2 C310.2 C311.2 C312.2 C313.2 C314.2 C315.2 C316.2 C317.2 C319.2 C320.2 C321.2 C322.2 C324.2 C325.2 C326.2 C327.2 C328.2 C329.2 C330.2 C331.2 C332.2 C333.2 C334.2 C335.2 C336.2 C337.2 C338.2 C339.2 C340.2 C341.2 C342.2 C343.2 C344.2 C345.2 C346.2 C347.2 C348.2 C349.2 C350.2 C351.2 C352.2 C353.2 C354.2 C355.2 C356.2 C357.2 C358.2 C359.2 C360.2 C361.2 C362.2 C363.2 C364.2 C365.2 C366.2 C367.2 C368.2 C369.2 C370.2 C371.2 C372.2 C373.2 C374.2 C375.2 C376.2 C377.2 C378.2 C379.2 C380.2 C381.2 C382.2 C383.2 C384.2 C385.2 C386.2 C387.2 C388.2 C389.2 C390.2 C391.2 C392.2 C393.2 C394.2 C395.2 C396.2 C397.2 C398.2 C399.2 C400.2 C401.2 C402.2 C403.2 C404.2 C405.2 C406.2 C407.2 C408.2 C409.2 C410.2 C411.2 C412.2 C413.2 C414.2 C415.2 C416.2 C417.2 C418.2 C419.2 C420.2 C424.2 C425.2 C426.2 C427.2 C428.2 C429.2 C430.2 C431.2 C432.2 C433.2 C434.2 C435.2 C436.2 C437.2 C438.2 C439.2 C440.2 C441.2 C442.2 C443.2 C444.2 C445.2 C446.2 C447.2 C448.2 C449.2 C450.2 C451.2 C452.2 C453.2 C454.2 C455.2 C456.2 C457.2 C458.2 C459.2 C460.2 C461.2 C462.2 C463.2 C464.2 C465.2 C466.2 C467.2 C468.2 C469.2 C470.2 C471.2 C472.2 C473.2 C474.2 C475.2 C476.2 C477.2 C478.2 C479.2 C480.2 C481.2 C482.2 C483.2 C484.2 C485.2 C486.2 C487.2 C488.2 C489.2 C490.2 C491.2 C492.2 C493.2 C494.2 C495.2 C496.2 C497.2 C498.2 C499.2 C500.2 C501.2 C502.2 C503.2 C505.2 C506.2 C507.2 C508.2 C509.2 C510.2 C511.2 C512.2 C513.2 C514.2 C515.2 C516.2 C517.2 C518.2 C519.2 C520.2 C521.2 C522.2 C523.2 C524.2 C525.2 C526.2 C527.2 C528.2 C529.2 C530.2 C531.2 C532.2 C533.2 C534.2 C535.2 C536.2 C537.2 C538.2 C539.2 C540.2 C541.2 C542.2 C543.2 C544.2 C545.2 C546.2 C547.2 C548.2 C549.2 C550.2 C551.2 C552.2 C553.2 C554.2 C555.2 C556.2 C557.2 C558.2 C559.2 C560.2 C565.2 C566.2 C567.2 C568.2 C569.2 C570.2 C571.2 C572.2 C573.2 C574.2 C575.2 C576.2 J1.16 J1.57 J1.MP1 J1.MP2 J1.MP3 J1.MP4 J2.4 J2.7 L32.1 R4.1 R5.1 R6.1 R7.1 R8.1 R9.1 R10.1 R12.1 R14.1 R23.1 R24.1 R85.1 R86.1 R87.1 R88.1 R89.1 R90.1 R91.1 R92.1 R93.1 R94.1 R95.1 R96.1 R97.1 R98.1 R107.1 R108.1 R109.1 R110.1 R111.1 R112.1 R113.1 R114.1 R126.2 R150.1 R151.1 R180.1 R181.1 R182.1 R183.1 R184.1 R185.1 R186.1 R187.1 R191.1 R192.1 R194.1 R195.1 R199.1 R219.1 R220.1 R221.1 R222.1 U1.A1 U1.A30 U1.AA6 U1.AA8 U1.AA10 U1.AA12 U1.AA14 U1.AA16 U1.AA18 U1.AA20 U1.AA22 U1.AA24 U1.AA29 U1.AB1 U1.AB7 U1.AB9 U1.AB11 U1.AB13 U1.AB15 U1.AB17 U1.AB19 U1.AB21 U1.AB23 U1.AB25 U1.AC6 U1.AC8 U1.AC10 U1.AC12 U1.AC14 U1.AC16 U1.AC18 U1.AC20 U1.AC22 U1.AC24 U1.AD3 U1.AD7 U1.AD9 U1.AD11 U1.AD13 U1.AD15 U1.AD17 U1.AD19 U1.AD21 U1.AD23 U1.AD25 U1.AD29 U1.AE6 U1.AE8 U1.AE10 U1.AE12 U1.AE14 U1.AE16 U1.AE18 U1.AE24 U1.AF7 U1.AF13 U1.AF16 U1.AF19 U1.AF21 U1.AF25 U1.AG4 U1.AG11 U1.AG14 U1.AG17 U1.AG20 U1.AG23 U1.AG26 U1.AG28 U1.AH10 U1.AH13 U1.AH16 U1.AH19 U1.AH22 U1.AH25 U1.AJ8 U1.AJ11 U1.AJ14 U1.AJ17 U1.AJ20 U1.AJ23 U1.AJ26 U1.AK1 U1.AK12 U1.AK15 U1.AK18 U1.AK21 U1.AK24 U1.AK27 U1.AK30 U1.C5 U1.C9 U1.C13 U1.C18 U1.C22 U1.C26 U1.D3 U1.D7 U1.D11 U1.D16 U1.D20 U1.D24 U1.D28 U1.F4 U1.F16 U1.G1 U1.G3 U1.G5 U1.G6 U1.G8 U1.G10 U1.G12 U1.G14 U1.G16 U1.G18 U1.G20 U1.G22 U1.G24 U1.H2 U1.H4 U1.H5 U1.H7 U1.H9 U1.H11 U1.H13 U1.H15 U1.H17 U1.H19 U1.H21 U1.H23 U1.J6 U1.J8 U1.J10 U1.J12 U1.J16 U1.J18 U1.J20 U1.J22 U1.J24 U1.J28 U1.K1 U1.K6 U1.K7 U1.K11 U1.K13 U1.K15 U1.K17 U1.K19 U1.K21 U1.K23 U1.K25 U1.L2 U1.L6 U1.L8 U1.L10 U1.L12 U1.L14 U1.L16 U1.L18 U1.L20 U1.L22 U1.L24 U1.M7 U1.M9 U1.M11 U1.M13 U1.M15 U1.M17 U1.M19 U1.M21 U1.M25 U1.N1 U1.N3 U1.N6 U1.N7 U1.N8 U1.N10 U1.N12 U1.N14 U1.N16 U1.N18 U1.N20 U1.N22 U1.N24 U1.N29 U1.P2 U1.P4 U1.P5 U1.P6 U1.P7 U1.P8 U1.P9 U1.P11 U1.P13 U1.P15 U1.P17 U1.P19 U1.P21 U1.P23 U1.P25 U1.R4 U1.R5 U1.R6 U1.R8 U1.R10 U1.R12 U1.R14 U1.R16 U1.R18 U1.R20 U1.R22 U1.R24 U1.T1 U1.T7 U1.T9 U1.T11 U1.T13 U1.T15 U1.T17 U1.T19 U1.T21 U1.T23 U1.T25 U1.U2 U1.U6 U1.U8 U1.U10 U1.U12 U1.U14 U1.U16 U1.U18 U1.U20 U1.U22 U1.U24 U1.U29 U1.V7 U1.V9 U1.V11 U1.V13 U1.V15 U1.V17 U1.V19 U1.V21 U1.V23 U1.V25 U1.W4 U1.W6 U1.W8 U1.W10 U1.W12 U1.W14 U1.W16 U1.W18 U1.W20 U1.W22 U1.W24 U1.Y5 U1.Y7 U1.Y9 U1.Y11 U1.Y13 U1.Y15 U1.Y17 U1.Y19 U1.Y21 U1.Y23 U1.Y25 U7.10 U8.A9 U8.B1 U8.B3 U8.B9 U8.D1 U8.D8 U8.E1 U8.E2 U8.E8 U8.F9 U8.G1 U8.G8 U8.G9 U8.J2 U8.J8 U8.M1 U8.M9 U8.P1 U8.P9 U8.T1 U8.T9 U9.A9 U9.B1 U9.B3 U9.B9 U9.D1 U9.D8 U9.E1 U9.E2 U9.E8 U9.F9 U9.G1 U9.G8 U9.G9 U9.J2 U9.J8 U9.M1 U9.M9 U9.P1 U9.P9 U9.T1 U9.T9 U10.A9 U10.B1 U10.B3 U10.B9 U10.D1 U10.D8 U10.E1 U10.E2 U10.E8 U10.F9 U10.G1 U10.G8 U10.G9 U10.J2 U10.J8 U10.M1 U10.M9 U10.P1 U10.P9 U10.T1 U10.T9 U11.A9 U11.B1 U11.B3 U11.B9 U11.D1 U11.D8 U11.E1 U11.E2 U11.E8 U11.F9 U11.G1 U11.G8 U11.G9 U11.J2 U11.J8 U11.M1 U11.M9 U11.P1 U11.P9 U11.T1 U11.T9 U12.A9 U12.B1 U12.B3 U12.B9 U12.D1 U12.D8 U12.E1 U12.E2 U12.E8 U12.F9 U12.G1 U12.G8 U12.G9 U12.J2 U12.J8 U12.M1 U12.M9 U12.P1 U12.P9 U12.T1 U12.T9 U14.2 U15.B1 U16.3 U17.C5 U17.F7 U17.K3 U17.K8
GND_CHASSIS: J2.S1 J2.S2 L32.2 U13.5 U13.10
K2L_ADC_SPI0CLK: R17.1
K2L_ADC_SPI0CLK_RS: R17.2 U1.L29
K2L_ADC_SPI0SCS0: R19.1
K2L_ADC_SPI0SCS0_RS: R19.2 U1.L30
K2L_ADC_SPI0SIMO: R18.1
K2L_ADC_SPI0SIMO_RS: R18.2 U1.L27
K2L_ADC_SPI0SOMI: U1.N27
K2L_ALTCORECLKN: R14.2 U1.AH30
K2L_ALTCORECLKP: R13.1 U1.AG30
K2L_AVDDA1_1V8_FILT: C439.1 C440.1 L21.1 U1.J23
K2L_AVDDA2_1V8_FILT: C455.1 C456.1 L23.1 U1.U25
K2L_AVDDA3_1V8_FILT: C459.1 C460.1 L24.1 U1.AF12
K2L_AVDDA4_1V8_FILT: C463.1 C464.1 L25.1 U1.AE26
K2L_AVDDA5_1V8_FILT: C467.1 C468.1 L26.1 U1.AF26
K2L_AVDDA10_6_1V8_FILT: C428.1 C429.1 C430.1 C431.1 C432.1 C433.1 C434.1 L20.1 U1.J11 U1.J14 U1.J17 U1.J21 U1.K8
K2L_BOOTCOMPLETE: R5.2 U1.AG3
K2L_CORECLKSEL0: R10.2 U1.AE27
K2L_CORECLKSEL1: R9.2 U1.AF27
K2L_CORESEL0_BOOTMODE13: R71.1 R85.2 U1.AE5
K2L_CORESEL1_BOOTMODE14: U1.AG6
K2L_CORESEL2_BOOTMODE15: U1.AH6
K2L_CS2_RXN0: U1.AJ25
K2L_CS2_RXN1: U1.AK26
K2L_CS2_RXP0: U1.AJ24
K2L_CS2_RXP1: U1.AK25
K2L_CS2_TXN0: U1.AH23
K2L_CS2_TXN1: U1.AG24
K2L_CS2_TXP0: U1.AH24
K2L_CS2_TXP1: U1.AG25
K2L_CS3_RXN0: U1.AK22
K2L_CS3_RXN1: U1.AK23
K2L_CS3_RXP0: U1.AJ21
K2L_CS3_RXP1: U1.AJ22
K2L_CS3_TXN0: U1.AH20
K2L_CS3_TXN1: U1.AG22
K2L_CS3_TXP0: U1.AH21
K2L_CS3_TXP1: U1.AG21
K2L_CVDD: C185.1 C186.1 C187.1 C188.1 C189.1 C190.1 C191.1 C192.1 C193.1 C194.1 C195.1 C196.1 C197.1 C198.1 C199.1 C200.1 C201.1 C202.1 C203.1 C204.1 C205.1 C206.1 C207.1 C208.1 C209.1 C210.1 C211.1 C212.1 C213.1 C214.1 C215.1 C216.1 C217.1 C218.1 C219.1 C220.1 C221.1 C222.1 C223.1 C224.1 C225.1 C226.1 C227.1 C228.1 C229.1 C230.1 C231.1 C232.1 C233.1 C234.1 C235.1 C236.1 C237.1 C238.1 C239.1 C240.1 C241.1 C242.1 C243.1 C244.1 C245.1 C246.1 C247.1 C248.1 C249.1 C250.1 C251.1 C252.1 C253.1 C254.1 C255.1 C256.1 C257.1 C258.1 C259.1 C260.1 C261.1 C262.1 C263.1 C264.1 C265.1 C266.1 C267.1 C268.1 C269.1 C270.1 C271.1 C272.1 C273.1 C274.1 C275.1 C276.1 C277.1 C278.1 C279.1 C280.1 C281.1 C282.1 C283.1 C292.1 C293.1 C294.1 C295.1 C296.1 C297.1 C298.1 C299.1 C300.1 C301.1 U1.AA9 U1.AA11 U1.AA13 U1.AA15 U1.AA17 U1.AA19 U1.AA21 U1.AB10 U1.AB12 U1.AB20 U1.AB22 U1.K12 U1.K14 U1.K16 U1.K18 U1.K20 U1.K22 U1.L9 U1.L11 U1.L13 U1.L15 U1.L17 U1.L19 U1.L21 U1.M14 U1.M18 U1.M20 U1.M22 U1.N9 U1.N13 U1.N17 U1.P10 U1.P12 U1.P14 U1.P18 U1.P22 U1.R11 U1.R13 U1.R15 U1.R17 U1.R19 U1.R21 U1.T12 U1.T14 U1.T16 U1.T18 U1.T20 U1.T22 U1.U11 U1.U13 U1.U15 U1.U17 U1.U19 U1.U21 U1.V12 U1.V14 U1.V16 U1.V18 U1.V20 U1.V22 U1.W9 U1.W11 U1.W13 U1.W17 U1.W19 U1.W21 U1.Y10 U1.Y12 U1.Y18 U1.Y20 U1.Y22
K2L_CVDD1V0: C302.1 C303.1 C304.1 C305.1 C306.1 C307.1 C308.1 C309.1 C310.1 C311.1 C312.1 C313.1 C314.1 C315.1 C316.1 C317.1 C319.1 C320.1 C321.1 C322.1 U1.AC21 U1.L7 U1.L23 U1.M10 U1.M12 U1.M16 U1.N11 U1.N15 U1.N19 U1.N21 U1.P16 U1.P20 U1.W15 U1.Y8 U1.Y14 U1.Y16
K2L_DAC_SPI1CLK: R20.1
K2L_DAC_SPI1CLK_RS: R20.2 U1.M26
K2L_DAC_SPI1SCS0: R22.1
K2L_DAC_SPI1SCS0_RS: R22.2 U1.M28
K2L_DAC_SPI1SIMO: R21.1
K2L_DAC_SPI1SIMO_RS: R21.2 U1.N26
K2L_DAC_SPI1SOMI: U1.L26
K2L_DDR3A0: R154.1 U1.C14 U8.N3 U9.N3 U10.N3 U11.N3 U12.N3
K2L_DDR3A1: R155.1 U1.D14 U8.P7 U9.P7 U10.P7 U11.P7 U12.P7
K2L_DDR3A2: R156.1 U1.A18 U8.P3 U9.P3 U10.P3 U11.P3 U12.P3
K2L_DDR3A3: R157.1 U1.E14 U8.N2 U9.N2 U10.N2 U11.N2 U12.N2
K2L_DDR3A4: R158.1 U1.C15 U8.P8 U9.P8 U10.P8 U11.P8 U12.P8
K2L_DDR3A5: R159.1 U1.A17 U8.P2 U9.P2 U10.P2 U11.P2 U12.P2
K2L_DDR3A6: R160.1 U1.D15 U8.R8 U9.R8 U10.R8 U11.R8 U12.R8
K2L_DDR3A7: R161.1 U1.B16 U8.R2 U9.R2 U10.R2 U11.R2 U12.R2
K2L_DDR3A8: R162.1 U1.B17 U8.T8 U9.T8 U10.T8 U11.T8 U12.T8
K2L_DDR3A9: R163.1 U1.D17 U8.R3 U9.R3 U10.R3 U11.R3 U12.R3
K2L_DDR3A10: R164.1 U1.B12 U8.L7 U9.L7 U10.L7 U11.L7 U12.L7
K2L_DDR3A11: R165.1 U1.B18 U8.R7 U9.R7 U10.R7 U11.R7 U12.R7
K2L_DDR3A12: R166.1 U1.C17 U8.N7 U9.N7 U10.N7 U11.N7 U12.N7
K2L_DDR3A13: R167.1 U1.B11 U8.T3 U9.T3 U10.T3 U11.T3 U12.T3
K2L_DDR3A14: R168.1 U1.E18 U8.T7 U9.T7 U10.T7 U11.T7 U12.T7
K2L_DDR3A15: R169.1 U1.E16
K2L_DDR3ACLKN: C3.1 C3.2 U1.G30
K2L_DDR3ACLKP: C4.1 C4.2 U1.F30
K2L_DDR3BA0: R173.1 U1.E11 U8.M2 U9.M2 U10.M2 U11.M2 U12.M2
K2L_DDR3BA1: R172.1 U1.F12 U8.N8 U9.N8 U10.N8 U11.N8 U12.N8
K2L_DDR3BA2: R171.1 U1.E12 U8.M3 U9.M3 U10.M3 U11.M3 U12.M3
K2L_DDR3CASZ: R176.1 U1.A13 U8.K3 U9.K3 U10.K3 U11.K3 U12.K3
K2L_DDR3CB0: U1.F19 U12.E3
K2L_DDR3CB1: U1.F20 U12.F7
K2L_DDR3CB2: U1.F18 U12.F2
K2L_DDR3CB3: U1.E20 U12.F8
K2L_DDR3CB4: U1.E19 U12.H3
K2L_DDR3CB5: U1.D19 U12.H8
K2L_DDR3CB6: U1.C19 U12.G2
K2L_DDR3CB7: U1.B19 U12.H7
K2L_DDR3CE0: R178.1 U1.A14 U8.L2 U9.L2 U10.L2 U11.L2 U12.L2
K2L_DDR3CKE0: R177.1 U1.E17 U8.K9 U9.K9 U10.K9 U11.K9 U12.K9
K2L_DDR3CLKOUTN0: R153.1 U1.A15 U8.K7 U9.K7 U10.K7 U11.K7 U12.K7
K2L_DDR3CLKOUTP0: R152.1 U1.A16 U8.J7 U9.J7 U10.J7 U11.J7 U12.J7
K2L_DDR3D0: U1.A21 U1.E1 U8.E3
K2L_DDR3D1: U1.B21 U1.C2 U8.F7
K2L_DDR3D2: U1.B2 U1.C21 U8.F2
K2L_DDR3D3: U1.C1 U1.D21 U8.F8
K2L_DDR3D4: U1.D1 U1.E22 U8.H3
K2L_DDR3D5: U1.D2 U1.E21 U8.H8
K2L_DDR3D6: U1.E2 U8.G2
K2L_DDR3D7: U1.E3 U8.H7
K2L_DDR3D8: U1.A5 U8.D7
K2L_DDR3D9: U1.D6 U8.C3
K2L_DDR3D10: U1.E6 U8.C8
K2L_DDR3D11: U1.B5 U8.C2
K2L_DDR3D12: U1.F6 U8.A7
K2L_DDR3D13: U1.D4 U8.A2
K2L_DDR3D14: U1.C4 U8.B8
K2L_DDR3D15: U1.F5 U8.A3
K2L_DDR3D16: U1.F8 U9.E3
K2L_DDR3D17: U1.E7 U9.F7
K2L_DDR3D18: U1.C6 U9.F2
K2L_DDR3D19: U1.B6 U9.F8
K2L_DDR3D20: U1.F7 U9.H3
K2L_DDR3D21: U1.E8 U9.H8
K2L_DDR3D22: U1.D8 U9.G2
K2L_DDR3D23: U1.C8 U9.H7
K2L_DDR3D24: U1.F10 U9.D7
K2L_DDR3D25: U1.D10 U9.C3
K2L_DDR3D26: U1.E10 U9.C8
K2L_DDR3D27: U1.C10 U9.C2
K2L_DDR3D28: U1.A9 U9.A7
K2L_DDR3D29: U1.A8 U9.A2
K2L_DDR3D30: U1.B9 U9.B8
K2L_DDR3D31: U1.E9 U9.A3
K2L_DDR3D32: U10.A3
K2L_DDR3D33: U10.B8
K2L_DDR3D34: U10.A2
K2L_DDR3D35: U10.A7
K2L_DDR3D36: U10.C2
K2L_DDR3D37: U10.C8
K2L_DDR3D38: U1.E23 U10.C3
K2L_DDR3D39: U1.F23 U10.D7
K2L_DDR3D40: U1.F25 U10.H7
K2L_DDR3D41: U1.D25 U10.G2
K2L_DDR3D42: U1.C23 U10.H8
K2L_DDR3D43: U1.E25 U10.H3
K2L_DDR3D44: U1.E24 U10.F8
K2L_DDR3D45: U1.D23 U10.F2
K2L_DDR3D46: U1.F24 U10.F7
K2L_DDR3D47: U1.B23 U10.E3
K2L_DDR3D48: U1.C25 U11.A3
K2L_DDR3D49: U1.B25 U11.B8
K2L_DDR3D50: U1.A25 U11.A2
K2L_DDR3D51: U1.A27 U11.A7
K2L_DDR3D52: U1.E26 U11.C2
K2L_DDR3D53: U1.E27 U11.C8
K2L_DDR3D54: U1.D27 U11.C3
K2L_DDR3D55: U1.B27 U11.D7
K2L_DDR3D56: U1.E30 U11.H7
K2L_DDR3D57: U1.E29 U11.G2
K2L_DDR3D58: U1.F29 U11.H8
K2L_DDR3D59: U1.D30 U11.H3
K2L_DDR3D60: U1.C30 U11.F8
K2L_DDR3D61: U1.D29 U11.F2
K2L_DDR3D62: U1.B28 U11.F7
K2L_DDR3D63: U1.A28 U11.E3
K2L_DDR3DQM0: U1.E4 U8.E7
K2L_DDR3DQM1: U1.E5 U8.D3
K2L_DDR3DQM2: U1.A6 U9.E7
K2L_DDR3DQM3: U1.B8 U9.D3
K2L_DDR3DQM4: U1.F22 U10.E7
K2L_DDR3DQM5: U1.A23 U10.D3
K2L_DDR3DQM6: U1.C27 U11.E7
K2L_DDR3DQM7: U1.E28 U11.D3
K2L_DDR3DQM8: U1.A19 U12.E7
K2L_DDR3DQSN0: U1.B3 U8.G3
K2L_DDR3DQSN1: U1.A4 U8.B7
K2L_DDR3DQSN2: U1.B7 U9.G3
K2L_DDR3DQSN3: U1.B10 U9.B7
K2L_DDR3DQSN4: U1.B22 U10.G3
K2L_DDR3DQSN5: U1.A24 U10.B7
K2L_DDR3DQSN6: U1.A26 U11.G3
K2L_DDR3DQSN7: U1.B29 U11.B7
K2L_DDR3DQSN8: U1.B20 U12.G3
K2L_DDR3DQSP0: U1.A3 U8.F3
K2L_DDR3DQSP1: U1.B4 U8.C7
K2L_DDR3DQSP2: U1.A7 U9.F3
K2L_DDR3DQSP3: U1.A10 U9.C7
K2L_DDR3DQSP4: U1.A22 U10.F3
K2L_DDR3DQSP5: U1.B24 U10.C7
K2L_DDR3DQSP6: U1.B26 U11.F3
K2L_DDR3DQSP7: U1.C29 U11.C7
K2L_DDR3DQSP8: U1.A20 U12.F3
K2L_DDR3ODT0: R179.1 U1.A12 U8.K1 U9.K1 U10.K1 U11.K1 U12.K1
K2L_DDR3RASZ: R175.1 U1.B13 U8.J3 U9.J3 U10.J3 U11.J3 U12.J3
K2L_DDR3RESETZ: R170.1 U1.E15 U8.T2 U9.T2 U10.T2 U11.T2 U12.T2
K2L_DDR3RZQ0: R180.2 U1.F13
K2L_DDR3RZQ1: R182.2 U1.F9
K2L_DDR3RZQ2: R181.2 U1.F21
K2L_DDR3VREF: C505.1 C506.1 C507.1 C517.1 C518.1 C528.1 C529.1 C539.1 C540.1 C550.1 C551.1 U1.F15 U8.H1 U8.M8 U9.H1 U9.M8 U10.H1 U10.M8 U11.H1 U11.M8 U12.H1 U12.M8
K2L_DDR3WEZ: R174.1 U1.D12 U8.L3 U9.L3 U10.L3 U11.L3 U12.L3
K2L_DDR_VTT: R154.2 R155.2 R156.2 R157.2 R158.2 R159.2 R160.2 R161.2 R162.2 R163.2 R164.2 R165.2 R166.2 R167.2 R168.2 R169.2 R170.2 R171.2 R172.2 R173.2 R174.2 R175.2 R176.2 R177.2 R178.2 R179.2
K2L_DFEIO0: U1.AH5
K2L_DFEIO1: U1.AJ5
K2L_DFEIO2: U1.AG7
K2L_DFEIO3: U1.AK5
K2L_DFEIO4: U1.AH7
K2L_DFEIO5: U1.AK6
K2L_DFEIO6: U1.AJ7
K2L_DFEIO7: U1.AG8
K2L_DFEIO8: U1.AK8
K2L_DFEIO9: U1.AK7
K2L_DFEIO10: U1.AG10
K2L_DFEIO11: U1.AJ6
K2L_DFEIO12: U1.AK10
K2L_DFEIO13: U1.AK9
K2L_DFEIO14: U1.AF9
K2L_DFEIO15: U1.AK11
K2L_DFEIO16: U1.AG9
K2L_DFEIO17: U1.AH9
K2L_DFESYNCIN_N1: U1.AF11
K2L_DFESYNCIN_P1: U1.AF10
K2L_DFESYNCOUT_N0: U1.AJ10
K2L_DFESYNCOUT_N1: U1.AH12
K2L_DFESYNCOUT_P0: U1.AJ9
K2L_DFESYNCOUT_P1: U1.AH11
K2L_DFESYSREFN: K4.1 U1.AF30
K2L_DFESYSREFP: K3.1 U1.AE30
K2L_DVDD1V5: U1.A2 U1.A29 U1.AA7 U1.B1 U1.B30 U1.C3 U1.C7 U1.C11 U1.C16 U1.C20 U1.C24 U1.C28 U1.D5 U1.D9 U1.D13 U1.D18 U1.D22 U1.D26 U1.G7 U1.G9 U1.G11 U1.G13 U1.G15 U1.G17 U1.G19 U1.G21 U1.G23 U1.G25 U1.H6 U1.H8 U1.H10 U1.H12 U1.H14 U1.H16 U1.H18 U1.H20 U1.H22 U1.H24 U1.J7 U1.J9 U1.J13 U1.J15 U1.J19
